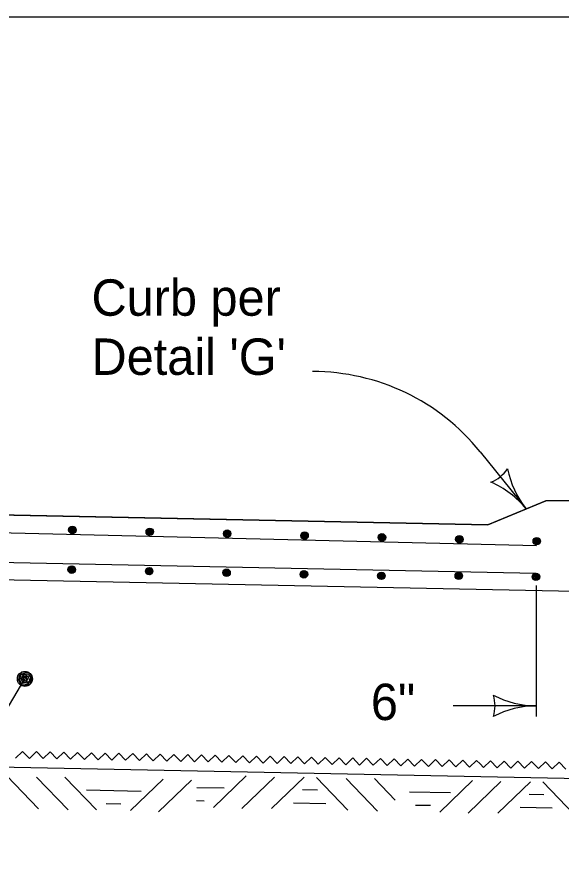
# Model space of a CAD drawing. Extents: x 5546 to 81668, y 3174 to 15999.
# Drawn here: x 17969.8 to 18209, y 9572.3 to 9944 of the extents above; entities that cross this region are included whole.
import ezdxf

# ---------------------------------------------------------------- set-up
doc = ezdxf.new("R2010")
doc.units = 0
for name, color, linetype in [('Level 61', 7, 'Continuous'), ('PS_BOLT', 7, 'Continuous'), ('PS_CONST', 7, 'Continuous'), ('PS_DAWA', 7, 'Continuous'), ('PS_DIM', 7, 'Continuous')]:
    doc.layers.add(name, color=color, linetype=linetype)

msp = doc.modelspace()

# ---------------------------------------------------------------- linework, layer by layer
at = {"layer": 'Level 61'}
msp.add_lwpolyline([(17332.52, 9944.02), (20467.53, 9944.02), (20467.53, 7924.02), (17332.52, 7924.02)], close=True, dxfattribs=at)
at = {"layer": 'PS_BOLT'}
msp.add_line((18198.1, 9699.22), (17466.58, 9714.38), dxfattribs=at)
at = {"layer": 'PS_CONST'}
for p, q in [((18173.42, 9752.81), (18193.69, 9727.64)), ((17927.27, 9575.92), (17973.29, 9652.89))]:
    msp.add_line(p, q, dxfattribs=at)
msp.add_lwpolyline([(17973.03, 9649.85), (17974.15, 9650.35), (17975.88, 9650.89), (17976.22, 9652.65), (17975.98, 9654.2), (17974.87, 9655.63), (17973.22, 9655.49), (17971.47, 9655.24), (17970.64, 9653.85), (17970.49, 9652.39), (17971.52, 9650.47), (17972.79, 9650.31), (17974.53, 9650.75), (17975.95, 9651.87), (17975.9, 9653.52), (17974.79, 9654.85), (17973.23, 9655), (17971.49, 9654.66), (17971.23, 9653.68), (17970.88, 9652.5), (17971.69, 9651.06), (17972.96, 9651.1), (17974.41, 9651.34), (17975.46, 9652.14), (17974.93, 9653.59), (17973.83, 9654.43), (17972.37, 9654.49), (17972, 9653.7), (17971.54, 9652.81), (17972.26, 9651.67), (17973.34, 9651.4), (17974.3, 9651.92), (17974.37, 9652.99), (17973.86, 9653.75), (17972.87, 9654.02), (17972.4, 9653.61), (17972.12, 9653.02), (17972.64, 9652.16), (17973.32, 9651.99), (17973.99, 9652.39), (17973.88, 9652.97), (17973.38, 9653.35), (17972.7, 9653.33), (17972.71, 9652.84), (17973.3, 9652.57)], dxfattribs=at)
msp.add_circle((17973.29, 9652.89), 3.31, dxfattribs=at)
for centre, radius, start, end in [((18099.79, 9693.53), 94.53, 38.8378, 90), ((18172.56, 9753.88), 15.52, 291.1048, 326.5715), ((18224.98, 9752.84), 40.18, 190.7656, 218.8381), ((18162.4, 9702.45), 40.18, 38.8381, 66.9106)]:
    msp.add_arc(centre, radius, start, end, dxfattribs=at)
at = {"layer": 'PS_DAWA'}
for p, q in [((18198.14, 9693.95), (18198.14, 9636.32)), ((18198.14, 9641.04), (18161.6, 9641.04))]:
    msp.add_line(p, q, dxfattribs=at)
for centre, radius, start, end in [((18164.46, 9641.05), 15.52, 342.2666, 17.7334), ((18198.14, 9681.22), 40.18, 241.9275, 270), ((18198.14, 9600.87), 40.18, 90, 118.0725)]:
    msp.add_arc(centre, radius, start, end, dxfattribs=at)
at = {"layer": 'PS_DIM'}
for p, q in [((18176.88, 9720.67), (17466.62, 9734.93)), ((17466.62, 9734.93), (18176.88, 9720.67)), ((18202.39, 9731.25), (18176.88, 9720.67)), ((18176.88, 9720.67), (18202.39, 9731.25)), ((18215.16, 9731.25), (18202.39, 9731.25)), ((18215.16, 9731.25), (18202.39, 9731.25)), ((17466.59, 9729.18), (18198.18, 9711.52)), ((17466.05, 9706.58), (18215.16, 9691.54)), ((17467.19, 9706.55), (18215.16, 9691.54)), ((17466.62, 9624.14), (18283.21, 9607.75)), ((17965.41, 9610.22), (17979.26, 9595.8)), ((17978.41, 9609.74), (17992.26, 9595.31)), ((17990.86, 9609.71), (18004.72, 9595.29)), ((18034.08, 9608.85), (18019.65, 9594.99)), ((18046.52, 9608.37), (18032.1, 9594.51)), ((18070.61, 9610.2), (18056.19, 9596.35)), ((18083.06, 9609.73), (18068.63, 9595.87)), ((18096.07, 9609.69), (18081.64, 9595.84)), ((18101.48, 9609.58), (18115.33, 9595.16)), ((18114.48, 9609.1), (18128.33, 9594.67)), ((18126.93, 9609.07), (18136.03, 9599.6)), ((18170.15, 9608.21), (18155.72, 9594.35)), ((18182.59, 9607.73), (18168.17, 9593.87)), ((18195.6, 9607.7), (18181.18, 9593.84)), ((18201.01, 9607.59), (18214.86, 9593.16))]:
    msp.add_line(p, q, dxfattribs=at)
for points in [[(17992.64, 9718.35), (17992.92, 9718.9), (17993.22, 9719.75), (17994.11, 9719.88), (17994.88, 9719.73), (17995.57, 9719.14), (17995.46, 9718.32), (17995.3, 9717.45), (17994.59, 9717.06), (17993.85, 9717.02), (17992.92, 9717.58), (17992.87, 9718.21), (17993.12, 9719.08), (17993.71, 9719.76), (17994.53, 9719.7), (17995.17, 9719.12), (17995.21, 9718.33), (17995.01, 9717.47), (17994.51, 9717.36), (17993.91, 9717.21), (17993.22, 9717.65), (17993.26, 9718.29), (17993.41, 9719.01), (17993.84, 9719.51), (17994.55, 9719.22), (17994.95, 9718.65), (17994.94, 9717.92), (17994.54, 9717.75), (17994.09, 9717.54), (17993.53, 9717.92), (17993.42, 9718.47), (17993.7, 9718.94), (17994.24, 9718.95), (17994.61, 9718.68), (17994.72, 9718.18), (17994.5, 9717.95), (17994.2, 9717.83), (17993.78, 9718.1), (17993.71, 9718.45), (17993.93, 9718.77), (17994.22, 9718.7), (17994.39, 9718.45), (17994.37, 9718.1), (17994.13, 9718.12), (17994, 9718.42)], [(18026.67, 9717.53), (18026.95, 9718.07), (18027.25, 9718.93), (18028.14, 9719.06), (18028.91, 9718.9), (18029.6, 9718.32), (18029.49, 9717.49), (18029.33, 9716.63), (18028.62, 9716.24), (18027.88, 9716.2), (18026.95, 9716.75), (18026.9, 9717.39), (18027.15, 9718.25), (18027.74, 9718.94), (18028.56, 9718.88), (18029.21, 9718.3), (18029.24, 9717.51), (18029.04, 9716.65), (18028.54, 9716.54), (18027.94, 9716.39), (18027.25, 9716.83), (18027.29, 9717.46), (18027.44, 9718.18), (18027.87, 9718.69), (18028.58, 9718.39), (18028.98, 9717.83), (18028.97, 9717.1), (18028.57, 9716.93), (18028.12, 9716.72), (18027.56, 9717.1), (18027.45, 9717.65), (18027.73, 9718.12), (18028.27, 9718.12), (18028.64, 9717.85), (18028.75, 9717.35), (18028.53, 9717.13), (18028.23, 9717), (18027.81, 9717.28), (18027.74, 9717.62), (18027.96, 9717.95), (18028.25, 9717.88), (18028.42, 9717.62), (18028.4, 9717.29), (18028.16, 9717.3), (18028.04, 9717.6)], [(18060.7, 9716.71), (18060.97, 9717.25), (18061.28, 9718.11), (18062.17, 9718.24), (18062.94, 9718.08), (18063.63, 9717.5), (18063.52, 9716.67), (18063.36, 9715.81), (18062.65, 9715.42), (18061.91, 9715.38), (18060.98, 9715.93), (18060.93, 9716.57), (18061.18, 9717.43), (18061.77, 9718.12), (18062.59, 9718.06), (18063.24, 9717.48), (18063.27, 9716.69), (18063.07, 9715.83), (18062.57, 9715.72), (18061.97, 9715.57), (18061.28, 9716.01), (18061.32, 9716.64), (18061.47, 9717.36), (18061.9, 9717.87), (18062.61, 9717.57), (18063.01, 9717), (18063, 9716.27), (18062.6, 9716.11), (18062.15, 9715.9), (18061.59, 9716.28), (18061.48, 9716.82), (18061.76, 9717.29), (18062.3, 9717.3), (18062.67, 9717.03), (18062.78, 9716.53), (18062.56, 9716.31), (18062.26, 9716.18), (18061.84, 9716.46), (18061.77, 9716.8), (18061.99, 9717.13), (18062.28, 9717.06), (18062.45, 9716.8), (18062.43, 9716.46), (18062.19, 9716.48), (18062.06, 9716.78)], [(18094.73, 9715.88), (18095, 9716.43), (18095.31, 9717.29), (18096.2, 9717.42), (18096.97, 9717.26), (18097.66, 9716.67), (18097.55, 9715.85), (18097.39, 9714.99), (18096.68, 9714.6), (18095.94, 9714.56), (18095.01, 9715.11), (18094.96, 9715.75), (18095.21, 9716.61), (18095.8, 9717.3), (18096.62, 9717.24), (18097.26, 9716.65), (18097.3, 9715.87), (18097.1, 9715.01), (18096.6, 9714.9), (18096, 9714.75), (18095.31, 9715.19), (18095.35, 9715.82), (18095.5, 9716.54), (18095.92, 9717.05), (18096.64, 9716.75), (18097.04, 9716.19), (18097.03, 9715.45), (18096.63, 9715.29), (18096.17, 9715.08), (18095.62, 9715.46), (18095.51, 9716), (18095.79, 9716.47), (18096.33, 9716.48), (18096.7, 9716.21), (18096.8, 9715.71), (18096.59, 9715.48), (18096.29, 9715.36), (18095.87, 9715.64), (18095.8, 9715.98), (18096.02, 9716.31), (18096.31, 9716.24), (18096.48, 9715.98), (18096.46, 9715.64), (18096.21, 9715.66), (18096.09, 9715.96)], [(18128.76, 9715.06), (18129.03, 9715.61), (18129.34, 9716.47), (18130.23, 9716.6), (18131, 9716.44), (18131.69, 9715.85), (18131.58, 9715.03), (18131.41, 9714.16), (18130.71, 9713.78), (18129.97, 9713.73), (18129.04, 9714.29), (18128.98, 9714.93), (18129.24, 9715.79), (18129.83, 9716.48), (18130.65, 9716.42), (18131.29, 9715.83), (18131.33, 9715.05), (18131.13, 9714.19), (18130.63, 9714.08), (18130.03, 9713.93), (18129.33, 9714.37), (18129.38, 9715), (18129.53, 9715.72), (18129.95, 9716.23), (18130.67, 9715.93), (18131.06, 9715.36), (18131.06, 9714.63), (18130.65, 9714.47), (18130.2, 9714.26), (18129.65, 9714.64), (18129.54, 9715.18), (18129.82, 9715.65), (18130.36, 9715.66), (18130.72, 9715.39), (18130.84, 9714.89), (18130.62, 9714.66), (18130.32, 9714.54), (18129.9, 9714.81), (18129.83, 9715.16), (18130.05, 9715.49), (18130.34, 9715.42), (18130.51, 9715.16), (18130.49, 9714.82), (18130.24, 9714.84), (18130.12, 9715.14)], [(18162.79, 9714.24), (18163.06, 9714.79), (18163.37, 9715.64), (18164.26, 9715.77), (18165.03, 9715.62), (18165.72, 9715.03), (18165.61, 9714.21), (18165.44, 9713.35), (18164.74, 9712.96), (18164, 9712.91), (18163.06, 9713.47), (18163.01, 9714.11), (18163.27, 9714.97), (18163.86, 9715.66), (18164.68, 9715.59), (18165.32, 9715.01), (18165.36, 9714.23), (18165.15, 9713.37), (18164.66, 9713.25), (18164.06, 9713.11), (18163.36, 9713.54), (18163.41, 9714.18), (18163.56, 9714.9), (18163.99, 9715.4), (18164.7, 9715.11), (18165.09, 9714.54), (18165.09, 9713.81), (18164.69, 9713.64), (18164.23, 9713.43), (18163.68, 9713.81), (18163.57, 9714.36), (18163.85, 9714.83), (18164.39, 9714.84), (18164.75, 9714.57), (18164.87, 9714.07), (18164.65, 9713.84), (18164.35, 9713.72), (18163.93, 9713.99), (18163.86, 9714.34), (18164.08, 9714.66), (18164.37, 9714.59), (18164.54, 9714.34), (18164.52, 9714), (18164.27, 9714.02), (18164.15, 9714.32)], [(18196.82, 9713.42), (18197.09, 9713.97), (18197.4, 9714.82), (18198.29, 9714.95), (18199.06, 9714.8), (18199.75, 9714.21), (18199.64, 9713.39), (18199.47, 9712.52), (18198.77, 9712.14), (18198.03, 9712.09), (18197.09, 9712.65), (18197.04, 9713.29), (18197.3, 9714.15), (18197.89, 9714.83), (18198.71, 9714.78), (18199.35, 9714.19), (18199.39, 9713.41), (18199.19, 9712.54), (18198.69, 9712.43), (18198.09, 9712.28), (18197.39, 9712.73), (18197.44, 9713.36), (18197.59, 9714.08), (18198.02, 9714.58), (18198.73, 9714.29), (18199.12, 9713.72), (18199.12, 9712.99), (18198.72, 9712.83), (18198.26, 9712.61), (18197.7, 9713), (18197.6, 9713.54), (18197.88, 9714.01), (18198.42, 9714.02), (18198.78, 9713.75), (18198.9, 9713.25), (18198.68, 9713.02), (18198.38, 9712.9), (18197.96, 9713.17), (18197.89, 9713.52), (18198.11, 9713.84), (18198.4, 9713.77), (18198.57, 9713.52), (18198.55, 9713.18), (18198.3, 9713.19), (18198.18, 9713.5)], [(17995.4, 9700.82), (17995.15, 9701.37), (17994.88, 9702.24), (17994, 9702.41), (17993.23, 9702.29), (17992.51, 9701.74), (17992.58, 9700.91), (17992.71, 9700.04), (17993.4, 9699.62), (17994.13, 9699.54), (17995.09, 9700.06), (17995.17, 9700.69), (17994.95, 9701.56), (17994.39, 9702.28), (17993.57, 9702.25), (17992.9, 9701.7), (17992.83, 9700.91), (17993, 9700.05), (17993.49, 9699.91), (17994.08, 9699.74), (17994.79, 9700.14), (17994.78, 9700.78), (17994.66, 9701.5), (17994.26, 9702.03), (17993.53, 9701.77), (17993.11, 9701.22), (17993.08, 9700.49), (17993.48, 9700.3), (17993.92, 9700.07), (17994.5, 9700.43), (17994.63, 9700.97), (17994.37, 9701.45), (17993.83, 9701.48), (17993.45, 9701.23), (17993.32, 9700.74), (17993.52, 9700.5), (17993.82, 9700.36), (17994.25, 9700.62), (17994.33, 9700.96), (17994.13, 9701.29), (17993.84, 9701.24), (17993.65, 9700.99), (17993.66, 9700.65), (17993.91, 9700.66), (17994.04, 9700.95)], [(18029.43, 9700.13), (18029.18, 9700.69), (18028.92, 9701.56), (18028.04, 9701.73), (18027.26, 9701.61), (18026.55, 9701.05), (18026.62, 9700.23), (18026.74, 9699.35), (18027.43, 9698.93), (18028.17, 9698.86), (18029.12, 9699.38), (18029.2, 9700.01), (18028.98, 9700.88), (18028.42, 9701.59), (18027.6, 9701.57), (18026.94, 9701.01), (18026.86, 9700.23), (18027.03, 9699.36), (18027.52, 9699.23), (18028.11, 9699.05), (18028.83, 9699.47), (18028.81, 9700.09), (18028.69, 9700.82), (18028.29, 9701.35), (18027.56, 9701.08), (18027.14, 9700.53), (18027.12, 9699.8), (18027.51, 9699.62), (18027.95, 9699.39), (18028.53, 9699.75), (18028.66, 9700.29), (18028.4, 9700.76), (18027.86, 9700.8), (18027.48, 9700.54), (18027.35, 9700.06), (18027.55, 9699.82), (18027.85, 9699.68), (18028.28, 9699.94), (18028.37, 9700.28), (18028.16, 9700.61), (18027.87, 9700.56), (18027.68, 9700.31), (18027.7, 9699.97), (18027.94, 9699.97), (18028.08, 9700.27)], [(18063.46, 9699.45), (18063.22, 9700.01), (18062.95, 9700.88), (18062.07, 9701.04), (18061.29, 9700.92), (18060.58, 9700.37), (18060.65, 9699.54), (18060.78, 9698.67), (18061.47, 9698.25), (18062.2, 9698.18), (18063.16, 9698.69), (18063.23, 9699.32), (18063.02, 9700.2), (18062.46, 9700.91), (18061.64, 9700.88), (18060.97, 9700.33), (18060.9, 9699.55), (18061.06, 9698.68), (18061.55, 9698.55), (18062.14, 9698.37), (18062.86, 9698.78), (18062.84, 9699.41), (18062.73, 9700.14), (18062.32, 9700.66), (18061.6, 9700.4), (18061.18, 9699.85), (18061.15, 9699.12), (18061.55, 9698.93), (18061.99, 9698.7), (18062.56, 9699.06), (18062.69, 9699.6), (18062.43, 9700.08), (18061.9, 9700.12), (18061.52, 9699.86), (18061.39, 9699.37), (18061.59, 9699.13), (18061.88, 9698.99), (18062.31, 9699.25), (18062.4, 9699.59), (18062.2, 9699.93), (18061.9, 9699.87), (18061.72, 9699.62), (18061.73, 9699.28), (18061.97, 9699.29), (18062.11, 9699.59)], [(18097.5, 9698.77), (18097.25, 9699.32), (18096.98, 9700.19), (18096.1, 9700.36), (18095.32, 9700.24), (18094.61, 9699.69), (18094.68, 9698.86), (18094.8, 9697.99), (18095.5, 9697.57), (18096.23, 9697.49), (18097.19, 9698.01), (18097.27, 9698.64), (18097.05, 9699.51), (18096.49, 9700.23), (18095.67, 9700.2), (18095, 9699.65), (18094.93, 9698.87), (18095.1, 9698), (18095.59, 9697.87), (18096.18, 9697.69), (18096.89, 9698.1), (18096.88, 9698.73), (18096.76, 9699.46), (18096.35, 9699.98), (18095.63, 9699.72), (18095.21, 9699.17), (18095.18, 9698.43), (18095.58, 9698.25), (18096.02, 9698.02), (18096.59, 9698.38), (18096.72, 9698.92), (18096.47, 9699.4), (18095.93, 9699.44), (18095.55, 9699.18), (18095.42, 9698.69), (18095.62, 9698.45), (18095.91, 9698.31), (18096.35, 9698.57), (18096.43, 9698.91), (18096.23, 9699.25), (18095.94, 9699.19), (18095.75, 9698.94), (18095.76, 9698.6), (18096, 9698.61), (18096.14, 9698.9)], [(18131.53, 9698.08), (18131.28, 9698.64), (18131.01, 9699.51), (18130.13, 9699.68), (18129.36, 9699.56), (18128.64, 9699), (18128.71, 9698.18), (18128.84, 9697.31), (18129.53, 9696.89), (18130.26, 9696.81), (18131.22, 9697.33), (18131.3, 9697.96), (18131.08, 9698.83), (18130.53, 9699.54), (18129.7, 9699.52), (18129.04, 9698.97), (18128.96, 9698.18), (18129.13, 9697.31), (18129.62, 9697.18), (18130.21, 9697), (18130.93, 9697.41), (18130.91, 9698.05), (18130.79, 9698.77), (18130.39, 9699.3), (18129.66, 9699.03), (18129.24, 9698.49), (18129.21, 9697.75), (18129.61, 9697.57), (18130.05, 9697.34), (18130.63, 9697.7), (18130.76, 9698.24), (18130.5, 9698.72), (18129.96, 9698.75), (18129.58, 9698.49), (18129.45, 9698), (18129.65, 9697.77), (18129.95, 9697.63), (18130.38, 9697.88), (18130.47, 9698.23), (18130.26, 9698.56), (18129.97, 9698.51), (18129.78, 9698.25), (18129.79, 9697.92), (18130.04, 9697.92), (18130.17, 9698.22)], [(18162.52, 9698.08), (18162.77, 9698.64), (18163.04, 9699.51), (18163.92, 9699.68), (18164.7, 9699.56), (18165.41, 9699), (18165.34, 9698.18), (18165.21, 9697.31), (18164.52, 9696.89), (18163.79, 9696.81), (18162.83, 9697.33), (18162.75, 9697.96), (18162.97, 9698.83), (18163.53, 9699.54), (18164.35, 9699.52), (18165.02, 9698.97), (18165.09, 9698.18), (18164.92, 9697.31), (18164.43, 9697.18), (18163.84, 9697), (18163.12, 9697.41), (18163.14, 9698.05), (18163.26, 9698.77), (18163.67, 9699.3), (18164.39, 9699.03), (18164.81, 9698.49), (18164.84, 9697.75), (18164.44, 9697.57), (18164, 9697.34), (18163.43, 9697.7), (18163.29, 9698.24), (18163.55, 9698.72), (18164.09, 9698.75), (18164.47, 9698.49), (18164.6, 9698), (18164.4, 9697.77), (18164.11, 9697.63), (18163.67, 9697.88), (18163.59, 9698.23), (18163.79, 9698.56), (18164.08, 9698.51), (18164.27, 9698.25), (18164.26, 9697.92), (18164.02, 9697.92), (18163.88, 9698.22)], [(18196.47, 9697.65), (18196.72, 9698.2), (18196.99, 9699.07), (18197.87, 9699.24), (18198.65, 9699.12), (18199.36, 9698.56), (18199.29, 9697.74), (18199.16, 9696.87), (18198.47, 9696.45), (18197.74, 9696.37), (18196.78, 9696.89), (18196.7, 9697.52), (18196.92, 9698.39), (18197.48, 9699.11), (18198.3, 9699.08), (18198.97, 9698.53), (18199.04, 9697.75), (18198.87, 9696.88), (18198.39, 9696.75), (18197.8, 9696.57), (18197.08, 9696.98), (18197.09, 9697.61), (18197.21, 9698.34), (18197.62, 9698.86), (18198.34, 9698.59), (18198.76, 9698.05), (18198.79, 9697.31), (18198.39, 9697.13), (18197.95, 9696.9), (18197.38, 9697.26), (18197.25, 9697.8), (18197.5, 9698.28), (18198.04, 9698.31), (18198.42, 9698.06), (18198.55, 9697.57), (18198.35, 9697.33), (18198.06, 9697.19), (18197.62, 9697.45), (18197.54, 9697.79), (18197.74, 9698.13), (18198.03, 9698.07), (18198.22, 9697.82), (18198.21, 9697.48), (18197.97, 9697.48), (18197.83, 9697.78)], [(17969.2, 9618.07), (17972.29, 9621.03), (17975.25, 9617.95), (17978.34, 9620.91), (17981.3, 9617.83), (17984.39, 9620.79), (17987.35, 9617.7), (17990.43, 9620.67), (17993.4, 9617.58), (17996.48, 9620.55), (17999.45, 9617.46), (18002.53, 9620.43), (18005.5, 9617.34), (18008.58, 9620.3), (18011.54, 9617.22), (18014.63, 9620.18), (18017.59, 9617.1), (18020.68, 9620.06), (18023.64, 9616.98), (18026.73, 9619.94), (18028.21, 9618.4)], [(18028.21, 9618.4), (18029.69, 9616.86), (18032.78, 9619.82), (18035.74, 9616.73), (18038.83, 9619.7), (18041.79, 9616.61), (18044.87, 9619.58), (18047.84, 9616.49), (18050.92, 9619.46), (18053.89, 9616.37), (18056.97, 9619.33), (18059.94, 9616.25), (18063.02, 9619.21), (18065.98, 9616.12), (18069.07, 9619.09), (18072.03, 9616.01), (18075.12, 9618.97), (18078.08, 9615.89), (18081.17, 9618.85), (18084.13, 9615.76), (18087.22, 9618.72), (18090.18, 9615.64), (18093.26, 9618.6), (18096.23, 9615.52), (18099.31, 9618.48), (18100.79, 9616.94)], [(18100.79, 9616.94), (18102.28, 9615.4), (18105.36, 9618.36), (18108.33, 9615.28), (18111.41, 9618.24), (18114.37, 9615.15), (18117.46, 9618.12), (18120.42, 9615.03), (18123.51, 9618), (18126.47, 9614.91), (18129.56, 9617.88), (18132.52, 9614.79), (18135.61, 9617.75), (18138.57, 9614.67), (18141.65, 9617.63), (18144.62, 9614.55), (18147.7, 9617.51), (18150.67, 9614.43), (18153.75, 9617.39), (18156.71, 9614.3), (18159.8, 9617.27), (18162.76, 9614.18), (18165.85, 9617.15), (18168.81, 9614.06), (18171.9, 9617.03), (18173.38, 9615.48)], [(18173.38, 9615.48), (18174.86, 9613.94), (18177.95, 9616.91), (18180.91, 9613.82), (18183.99, 9616.78), (18186.96, 9613.7), (18190.04, 9616.66), (18193.01, 9613.58), (18196.09, 9616.54), (18199.06, 9613.46), (18202.14, 9616.42), (18205.1, 9613.33), (18208.19, 9616.3), (18211.15, 9613.21)], [(18048.9, 9605.16), (18060.92, 9604.92)], [(18000.33, 9604.05), (18024.39, 9603.56)], [(18095.4, 9604.21), (18101.93, 9604.08)], [(18142.39, 9603.29), (18160.46, 9602.92)], [(18194.93, 9602.21), (18201.46, 9602.08)], [(18008.98, 9598.07), (18015.51, 9597.94)], [(18048.78, 9599.37), (18052.04, 9599.3)], [(18091.45, 9598.43), (18105.64, 9598.14)], [(18145.05, 9597.43), (18151.58, 9597.3)], [(18190.98, 9596.43), (18205.17, 9596.15)]]:
    msp.add_lwpolyline(points, dxfattribs=at)
for centre in [(17994.16, 9718.41), (18028.19, 9717.59), (18062.22, 9716.76), (18096.25, 9715.94), (18130.28, 9715.12), (18164.31, 9714.3), (18198.34, 9713.48), (17993.88, 9700.94), (18027.92, 9700.26), (18061.95, 9699.57), (18095.98, 9698.89), (18130.01, 9698.21), (18164.04, 9698.21), (18197.99, 9697.77)]:
    msp.add_circle(centre, 1.65, dxfattribs=at)

# ---------------------------------------------------------------- texts
at = {"layer": 'PS_CONST'}
for s, p in [('Curb per ', (18002.58, 9812.6)), ("Detail 'G'", (18002.58, 9786.6))]:
    msp.add_text(s, height=16, dxfattribs=at).set_placement(p)
at = {"layer": 'PS_DAWA'}
msp.add_text('6"', height=16, dxfattribs=at).set_placement((18125.41, 9634.79))

doc.saveas('drawing.dxf')
